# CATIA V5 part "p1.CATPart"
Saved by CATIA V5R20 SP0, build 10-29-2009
Part number: p1
Publications: "Point.1", "Point.2", "Point.3", "Point.4", "Point.5", "Point.6", "Point.7", "Point.8", "Point.9"
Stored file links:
  D:\Dropbox\IAO_2011\MMS_GR2\IAO_2011_1439_jlicbarski\p1.CATPart

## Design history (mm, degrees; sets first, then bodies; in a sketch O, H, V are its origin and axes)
Parameters
  LENGTH = 120 mm
AxisSystem1: origin (0, 0, 0), X (1, 0, 0), Y (0, 1, 0), Z (0, 0, 1)
Body1 (main body)
  Point1: (0, -50, 0), in AxisSystem1
  Point2: (0, -50, 20), in AxisSystem1
  Point3: (0, -50, 60), in AxisSystem1
  Point4: (0, -50, 80), in AxisSystem1
  Point5: (0, -20, 40), in AxisSystem1
  Point6: (0, 40, 80), in AxisSystem1
  Point7: (0, 40, 60), in AxisSystem1
  Point8: (0, 62, 86), in AxisSystem1
  Point9: (-12.5, 30, 120 {= LENGTH}), in AxisSystem1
